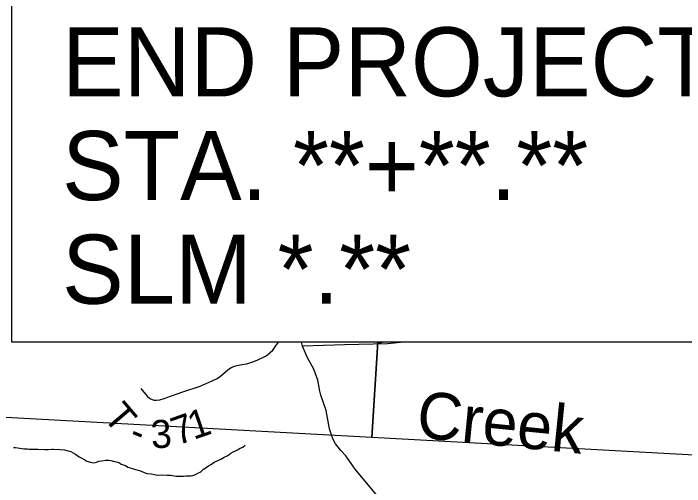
# Model space of a CAD drawing. Extents: x 0 to 34, y 0 to 22.
# Drawn here: x 6.056 to 7.417, y 15.766 to 16.725 of the extents above; entities that cross this region are included whole.
import ezdxf

# ---------------------------------------------------------------- set-up
doc = ezdxf.new("R2010")
doc.units = 0
for name, color, linetype in [('GM_X_County_Road', 7, 'Continuous'), ('GM_X_Minor_River', 7, 'Continuous'), ('GM_X_Minor_River_Text', 7, 'Continuous'), ('GM_X_Section', 7, 'Continuous'), ('GM_X_Township_Road', 7, 'Continuous'), ('GM_X_Township_Road_Text', 7, 'Continuous'), ('GM_X_Township_ROW', 7, 'Continuous'), ('SH_Text', 7, 'Continuous')]:
    doc.layers.add(name, color=color, linetype=linetype)

msp = doc.modelspace()

# ---------------------------------------------------------------- linework, layer by layer
at = {"layer": 'GM_X_County_Road'}
for points in [[(6.6777, 15.9594), (6.6731, 15.9821), (6.665, 16.0044), (6.6524, 16.0272), (6.6423, 16.051), (6.6404, 16.0591)], [(6.9708, 15.4567), (6.9637, 15.4824), (6.9534, 15.5048), (6.9321, 15.5336), (6.9109, 15.5617), (6.8907, 15.5856), (6.8638, 15.6464), (6.8539, 15.6885), (6.8509, 15.7003), (6.843, 15.7128), (6.8305, 15.7201), (6.8191, 15.7261), (6.8058, 15.7334), (6.7487, 15.8017), (6.73, 15.8288), (6.7203, 15.8396), (6.709, 15.853), (6.704, 15.8632), (6.6972, 15.8837), (6.6903, 15.9208), (6.6792, 15.9517), (6.6777, 15.9594)]]:
    msp.add_lwpolyline(points, dxfattribs=at)
at = {"layer": 'GM_X_Minor_River'}
for points in [[(6.8055, 16.0591), (6.7968, 16.0562), (6.7915, 16.0547)], [(6.1821, 15.8322), (6.1896, 15.8267), (6.1937, 15.8247), (6.2009, 15.8208), (6.2054, 15.8181), (6.2125, 15.8157), (6.2159, 15.8149), (6.2193, 15.8144), (6.2246, 15.8159), (6.2296, 15.8181), (6.2349, 15.8187), (6.2433, 15.8197), (6.2497, 15.8196), (6.2535, 15.8192), (6.2614, 15.8175), (6.2678, 15.8159), (6.2712, 15.8143), (6.2749, 15.8116), (6.2836, 15.8088), (6.2885, 15.8056), (6.2979, 15.8032), (6.3035, 15.8012), (6.3137, 15.798), (6.3212, 15.7948), (6.3273, 15.7932), (6.3363, 15.7919), (6.3424, 15.7907), (6.3477, 15.7898), (6.356, 15.7901), (6.3681, 15.7895), (6.3749, 15.7894), (6.3859, 15.7876), (6.4007, 15.7874), (6.4064, 15.7881), (6.4166, 15.7883), (6.42, 15.789), (6.4257, 15.7908), (6.4303, 15.7937), (6.436, 15.7963), (6.4414, 15.8015), (6.4449, 15.8037), (6.4514, 15.8086), (6.4575, 15.8115), (6.4629, 15.816), (6.477, 15.8218), (6.4832, 15.8259), (6.4896, 15.8284), (6.4935, 15.8314), (6.4973, 15.834), (6.5019, 15.8369), (6.5065, 15.8388), (6.5103, 15.841), (6.5157, 15.8443), (6.521, 15.8461), (6.526, 15.8506)], [(6.0562, 15.8457), (6.0604, 15.8456), (6.0694, 15.844), (6.0774, 15.8431), (6.0846, 15.843), (6.088, 15.8425), (6.099, 15.8423), (6.1058, 15.8422), (6.1202, 15.8416), (6.127, 15.8415), (6.1342, 15.8421), (6.1376, 15.842), (6.1505, 15.8414), (6.1595, 15.8409), (6.1675, 15.8389), (6.1724, 15.8373), (6.1821, 15.8322)]]:
    msp.add_lwpolyline(points, dxfattribs=at)
at = {"layer": 'GM_X_Section'}
for points in [[(6.795, 16.0591), (6.7831, 15.8661), (5.6567, 15.9275), (5.7237, 16.9481), (6.8455, 16.8788), (6.8391, 16.7743)], [(6.8391, 16.7743), (6.8455, 16.8788), (7.9583, 16.8099), (7.9053, 15.8044), (6.7831, 15.8661), (6.795, 16.0591)]]:
    msp.add_lwpolyline(points, dxfattribs=at)
at = {"layer": 'GM_X_Township_Road'}
msp.add_lwpolyline([(6.3147, 15.965), (6.3272, 15.9495), (6.3328, 15.945), (6.3411, 15.9416), (6.3463, 15.9412), (6.3529, 15.9419), (6.362, 15.9445), (6.3769, 15.9499), (6.4016, 15.9588), (6.4349, 15.9701), (6.4589, 15.9803), (6.4691, 15.9852), (6.4761, 15.99), (6.4907, 16.0026), (6.4974, 16.0073), (6.5066, 16.0113), (6.5161, 16.0133), (6.5237, 16.0147), (6.5296, 16.0149), (6.5418, 16.0194), (6.5504, 16.0226), (6.5674, 16.0306), (6.5712, 16.0332), (6.5818, 16.0428), (6.5875, 16.0511), (6.5936, 16.0591)], dxfattribs=at)
at = {"layer": 'GM_X_Township_ROW'}
msp.add_lwpolyline([(6.8478, 16.0591), (6.8144, 16.0555), (6.7271, 16.0537), (6.6423, 16.051)], dxfattribs=at)
at = {"layer": 'SH_Text'}
msp.add_lwpolyline([(6.0532, 16.7743), (7.8426, 16.7743), (7.8426, 16.0591), (6.0532, 16.0591)], close=True, dxfattribs=at)

# ---------------------------------------------------------------- texts
at = {"layer": 'GM_X_Minor_River_Text'}
msp.add_text('Creek', height=0.0947, rotation=354.2984, dxfattribs=at).set_placement((6.871, 15.8663))
at = {"layer": 'GM_X_Township_Road_Text'}
for s, rotation, p in [('T', 310.5121, (6.2365, 15.9062)), ('1', 18.9887, (6.4214, 15.8608)), ('7', 19.6877, (6.3886, 15.8491)), ('3', 3.5534, (6.3366, 15.8434)), ('-', 337.6153, (6.2876, 15.8569))]:
    msp.add_text(s, height=0.0568, rotation=rotation, dxfattribs=at).set_placement(p)
at = {"layer": 'SH_Text'}
for s, p in [('END PROJECT', (6.1549, 16.5567)), ('STA. **+**.**', (6.1549, 16.3467)), ('SLM *.**', (6.1549, 16.1367))]:
    msp.add_text(s, height=0.14, dxfattribs=at).set_placement(p)

doc.saveas('drawing.dxf')
